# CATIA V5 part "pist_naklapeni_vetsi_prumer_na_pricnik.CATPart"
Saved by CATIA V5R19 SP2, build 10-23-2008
Part number: pist_naklapeni_vetsi_prumer_na_pricnik
Bounding box of the stored display mesh (mm): x -54.985 to 54.985, y -42.705 to 442.295, z -55 to 55
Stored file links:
  D:\Catia fórum\Modely - Otazky\Naklapeni_oprava\pist_naklapeni_vetsi_prumer_na_pricnik.CATPart
  C:\Program Files\Dassault Systemes\B19\intel_a\startup\materials\Catalog.CATMaterial
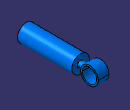
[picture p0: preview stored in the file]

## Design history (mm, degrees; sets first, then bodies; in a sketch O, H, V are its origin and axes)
Body1 (main body)
  Sketch1 on yz-plane, origin (0, 0, 0), H (0, 1, 0), V (0, 0, 1)
    axis line L1 (371.4804, 0) -> (-60.2057, 0)
    point P1 (371.4804, 0)
    point P3 (297.2948, 55)
    line L2 (297.2948, 55) -> (-42.7052, 55)
    line L3 (-42.7052, 55) -> (-42.7052, 50)
    line L4 (-42.7052, 50) -> (287.2948, 50)
    line L5 (287.2948, 50) -> (287.2948, 0)
    point P7 (287.2948, 0)
    line L6 (297.2948, 55) -> (297.2948, 0)
    point P8 (297.2948, 0)
    "Radius" L4 L1 = 50
    "Radius" L1 L2 = 55
    distance L5 L3 = 330
    distance L3 P3 = 340
    coincidence: P1 H, P7 L1, P8 L1
    horizontal: L1 H, L2 H, L4 H
    vertical: L3 V, L5 V, L6 V
  Shaft1: profile Sketch1, axis Sketch1.L1, angle 360
  Sketch2 on yz-plane, origin (0, 0, 0), H (0, 1, 0), V (0, 0, 1)
    circle A1 centre (387.2948, 0) radius 45
    point P1 (387.2948, 0)
    circle A2 centre (387.2948, 0) radius 55
    reference projected line E1 (297.2948, -45) -> (297.2948, 45) from edge [face of Shaft1 from Sketch1.L6 | face of Shaft1 from Sketch1.L2]
    radius A1 = 45
    radius A2 = 55
    distance P1 E1 = 90
    coincidence: P1 H
  Pad1: profile Sketch2, direction (1, 0, 0), length 34, mirrored extent
  Sketch3 on face of Shaft1 from Sketch1.L6, origin (0, 297.2948, 0), H (-1, 0, 0), V (0, 0, 1)
    circle A1 centre (0, 0) radius 20
    radius A1 = 20
  Pad2: profile Sketch3, direction (0, 1, 0), up to the existing solid (limit type 2)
